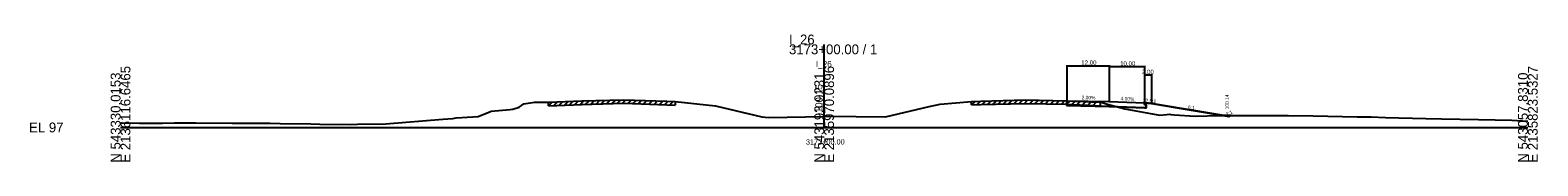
# Model space of a CAD drawing. Extents: x -13101 to 4803, y -924 to 22390.
# Drawn here: x -25.7 to 402.8, y 18990.3 to 19026.4 of the extents above; entities that cross this region are included whole.
import ezdxf

# ---------------------------------------------------------------- set-up
doc = ezdxf.new("R2010")
doc.units = 0
for name, color, linetype in [('RD_GPK_XS_Cell', 7, 'Continuous'), ('RD_XD_TX_Width', 7, 'Continuous'), ('RD_XS_Base', 7, 'Continuous'), ('RD_XS_EarthShd', 7, 'Continuous'), ('RD_XS_EwShp', 7, 'Continuous'), ('RD_XS_ExGround', 7, 'Continuous'), ('RD_XS_ExPaveRet', 7, 'Continuous'), ('RD_XS_OSBase', 7, 'Continuous'), ('RD_XS_Pave', 7, 'Continuous'), ('RD_XS_TieSlope', 7, 'Continuous'), ('RD_XS_TX_Baseline', 7, 'Continuous'), ('RD_XS_TX_Elev_EX', 7, 'Continuous'), ('RD_XS_TX_Elev_PR', 7, 'Continuous'), ('RD_XS_TX_ShdSlope', 7, 'Continuous'), ('RD_XS_TX_Slope', 7, 'Continuous'), ('RD_XS_TX_Station', 7, 'Continuous')]:
    doc.layers.add(name, color=color, linetype=linetype)

msp = doc.modelspace()

# ---------------------------------------------------------------- linework, layer by layer
at = {"layer": 'RD_GPK_XS_Cell'}
for p, q in [((200, 19000), (200, 19023.6)), ((0, 19000), (200, 19000)), ((200, 19000), (400, 19000))]:
    msp.add_line(p, q, dxfattribs=at)
at = {"layer": 'RD_XD_TX_Width'}
for p, q in [((269, 19017.75), (269, 19007.8)), ((269, 19017.55), (281, 19017.55)), ((281, 19017.75), (281, 19007.56)), ((281, 19017.51), (281, 19007.56)), ((281, 19017.31), (291, 19017.31)), ((291, 19017.51), (291, 19007.16)), ((291, 19015.11), (291, 19007.16)), ((291, 19014.91), (293, 19014.91)), ((293, 19015.11), (293, 19007))]:
    msp.add_line(p, q, dxfattribs=at)
at = {"layer": 'RD_XS_Base'}
for p, q in [((269, 19006.2), (281, 19005.96)), ((281, 19005.96), (291, 19005.56))]:
    msp.add_line(p, q, dxfattribs=at)
at = {"layer": 'RD_XS_EarthShd'}
msp.add_line((291, 19006.96), (293, 19006.8), dxfattribs=at)
at = {"layer": 'RD_XS_EwShp'}
for points in [[(279.3, 19006.98), (280.13, 19006.75), (283.37, 19005.87), (281, 19005.96), (269, 19006.2), (269, 19007.2), (269, 19007.6), (278.45, 19007.19)], [(305.42, 19003.17), (312.37, 19003.36), (313.6, 19003.37), (293, 19006.8), (291, 19006.96), (291, 19006.56), (291.5, 19006.54), (291.5, 19005.54), (291, 19005.56), (283.37, 19005.87), (285.41, 19005.31), (292.75, 19003.99), (295.41, 19003.54), (297.38, 19003.66), (298.11, 19003.74), (298.53, 19003.65), (299.46, 19003.58)], [(313.6, 19003.37), (315, 19003.14), (315.49, 19003.39)]]:
    msp.add_lwpolyline(points, close=True, dxfattribs=at)
at = {"layer": 'RD_XS_ExGround'}
msp.add_lwpolyline([(0, 19001.28), (5.34, 19001.2), (11.95, 19001.25), (15.35, 19001.28), (21.44, 19001.29), (31.77, 19001.18), (35.35, 19001.26), (42.49, 19001.18), (45.35, 19001.12), (54.1, 19000.99), (56.61, 19000.96), (65.36, 19000.83), (67.37, 19000.9), (75.36, 19001.06), (91.6, 19002.4), (94.43, 19002.58), (95.37, 19002.72), (96.96, 19002.82), (101.68, 19003.12), (104.72, 19004.39), (105.37, 19004.67), (110.72, 19005.09), (111.48, 19005.17), (113.31, 19005.75), (114.64, 19006.67), (117.7, 19007.2), (120.73, 19007.19), (121.64, 19007.19), (131.09, 19007.55), (143.04, 19007.87), (155.31, 19007.44), (157.62, 19007.35), (169.09, 19006.11), (182.28, 19003.03), (184.17, 19002.85), (200, 19003.15), (200.78, 19003.17), (217.38, 19003.05), (229.87, 19005.92), (232.99, 19006.61), (241.91, 19007.39), (244.55, 19007.48), (257.11, 19007.84), (268.94, 19007.61), (278.45, 19007.19), (279.3, 19006.98), (280.13, 19006.75), (285.41, 19005.31), (292.75, 19003.99), (295.41, 19003.54), (297.38, 19003.66), (298.11, 19003.74), (298.53, 19003.65), (299.46, 19003.58), (305.42, 19003.17), (312.37, 19003.36), (318.68, 19003.41), (325.42, 19003.36), (331.9, 19003.42), (338.99, 19003.31), (351.46, 19003.03), (355.43, 19003.01), (359.56, 19002.87), (371, 19002.55), (375.43, 19002.45), (385.93, 19002.25), (395.44, 19002.06), (400, 19001.82)], dxfattribs=at)
at = {"layer": 'RD_XS_ExPaveRet'}
for p, q in [((121.64, 19006.19), (122.68, 19007.23)), ((121.64, 19006.19), (121.64, 19007.19)), ((121.64, 19006.19), (131.09, 19006.55)), ((123.14, 19006.25), (124.18, 19007.29)), ((124.64, 19006.31), (125.68, 19007.35)), ((126.14, 19006.36), (127.18, 19007.4)), ((127.64, 19006.42), (128.68, 19007.46)), ((129.14, 19006.48), (130.18, 19007.52)), ((130.64, 19006.53), (131.68, 19007.57)), ((131.09, 19006.55), (143.04, 19006.87)), ((132.14, 19006.58), (133.17, 19007.61)), ((133.64, 19006.62), (134.67, 19007.65)), ((135.14, 19006.66), (136.17, 19007.68)), ((136.64, 19006.7), (137.67, 19007.72)), ((138.14, 19006.74), (139.17, 19007.76)), ((139.64, 19006.78), (140.67, 19007.8)), ((141.14, 19006.82), (142.17, 19007.84)), ((142.64, 19006.86), (143.63, 19007.84)), ((143.04, 19006.87), (155.31, 19006.44)), ((144.14, 19006.83), (145.11, 19007.79)), ((145.64, 19006.77), (146.61, 19007.74)), ((147.14, 19006.72), (148.11, 19007.69)), ((148.64, 19006.67), (149.61, 19007.64)), ((150.14, 19006.62), (151.11, 19007.58)), ((151.64, 19006.57), (152.61, 19007.53)), ((153.14, 19006.51), (154.11, 19007.48)), ((154.64, 19006.46), (155.61, 19007.43)), ((155.31, 19006.44), (157.62, 19006.35)), ((156.14, 19006.41), (157.11, 19007.37)), ((157.62, 19007.35), (157.62, 19006.35)), ((241.91, 19006.39), (242.94, 19007.42)), ((241.91, 19006.39), (241.91, 19007.39)), ((241.91, 19006.39), (244.55, 19006.48)), ((243.41, 19006.44), (244.44, 19007.47)), ((244.55, 19006.48), (257.11, 19006.84)), ((244.91, 19006.49), (245.94, 19007.52)), ((246.41, 19006.53), (247.44, 19007.56)), ((247.91, 19006.58), (248.94, 19007.61)), ((249.41, 19006.62), (250.44, 19007.65)), ((250.91, 19006.66), (251.94, 19007.69)), ((252.41, 19006.71), (253.44, 19007.74)), ((253.91, 19006.75), (254.94, 19007.78)), ((255.41, 19006.79), (256.44, 19007.82)), ((256.91, 19006.84), (257.9, 19007.83)), ((257.11, 19006.84), (268.94, 19006.61)), ((258.41, 19006.82), (259.39, 19007.8)), ((259.91, 19006.79), (260.89, 19007.77)), ((261.41, 19006.76), (262.39, 19007.74)), ((262.91, 19006.73), (263.89, 19007.71)), ((264.41, 19006.7), (265.39, 19007.68)), ((265.91, 19006.67), (266.89, 19007.65)), ((267.41, 19006.64), (268.39, 19007.62)), ((268.91, 19006.61), (269.87, 19007.57)), ((268.94, 19006.61), (278.45, 19006.19)), ((270.41, 19006.54), (271.36, 19007.5)), ((271.91, 19006.48), (272.86, 19007.44)), ((273.41, 19006.41), (274.36, 19007.37)), ((274.91, 19006.35), (275.86, 19007.31)), ((276.41, 19006.28), (277.36, 19007.24)), ((278.45, 19007.19), (278.45, 19006.19))]:
    msp.add_line(p, q, dxfattribs=at)
at = {"layer": 'RD_XS_OSBase'}
for p, q in [((269, 19007.2), (269, 19007.6)), ((269, 19006.2), (269, 19007.2)), ((291, 19006.56), (291, 19006.96)), ((291.5, 19006.54), (291, 19006.56)), ((291, 19005.56), (291.5, 19005.54)), ((291.5, 19005.54), (291.5, 19006.54))]:
    msp.add_line(p, q, dxfattribs=at)
at = {"layer": 'RD_XS_Pave'}
for p, q in [((269, 19007.6), (281, 19007.36)), ((281, 19007.36), (291, 19006.96))]:
    msp.add_line(p, q, dxfattribs=at)
at = {"layer": 'RD_XS_TieSlope'}
for p, q in [((293, 19006.8), (315, 19003.14)), ((315, 19003.14), (315.49, 19003.39))]:
    msp.add_line(p, q, dxfattribs=at)

# ---------------------------------------------------------------- texts
at = {"layer": 'RD_GPK_XS_Cell'}
for s, p in [('3173+00.00 / 1', (190, 19020.8)), ('I_26', (190, 19023.6)), ('EL 97', (-26, 18998.6))]:
    msp.add_text(s, height=2.8, dxfattribs=at).set_placement(p)
for s, p in [('N 543330.0153', (0, 18990)), ('E 2136116.6465', (2.8, 18990)), ('N 543193.9231', (200, 18990)), ('E 2135970.0896', (202.8, 18990)), ('N 543057.8310', (400, 18990)), ('E 2135823.5327', (402.8, 18990))]:
    msp.add_text(s, height=2.8, rotation=90, dxfattribs=at).set_placement(p)
at = {"layer": 'RD_XD_TX_Width'}
for s, p in [('12.00', (273.07, 19017.8)), ('10.00', (284.11, 19017.56)), ('2.00', (290.31, 19015.16))]:
    msp.add_text(s, height=1.25, dxfattribs=at).set_placement(p)
at = {"layer": 'RD_XS_TX_Baseline'}
msp.add_text('I_26', height=1.75, dxfattribs=at).set_placement((197.6, 19017.15))
at = {"layer": 'RD_XS_TX_Elev_EX'}
msp.add_text('100.15', height=2, rotation=90, dxfattribs=at).set_placement((199.5, 19004.15))
at = {"layer": 'RD_XS_TX_Elev_PR'}
msp.add_text('100.14', height=1, rotation=90, dxfattribs=at).set_placement((315, 19005.14))
at = {"layer": 'RD_XS_TX_ShdSlope'}
msp.add_text('12.5:1', height=1, rotation=355.4261, dxfattribs=at).set_placement((290.51, 19007.25))
msp.add_text('12.5:1', height=1, rotation=355.4261, dxfattribs=at).set_placement((290.51, 19007.25))
at = {"layer": 'RD_XS_TX_Slope'}
for s, rotation, p in [('2.00%', 358.8542, (273.16, 19008.02)), ('4.00%', 357.7094, (284.22, 19007.74)), ('6:1', 350.5377, (303.35, 19005.33)), ('2:1', 26.5651, (314.46, 19003.15))]:
    msp.add_text(s, height=1, rotation=rotation, dxfattribs=at).set_placement(p)
at = {"layer": 'RD_XS_TX_Station'}
msp.add_text('3173+00.00', height=1.5, dxfattribs=at).set_placement((194.81, 18995.15))

doc.saveas('drawing.dxf')
